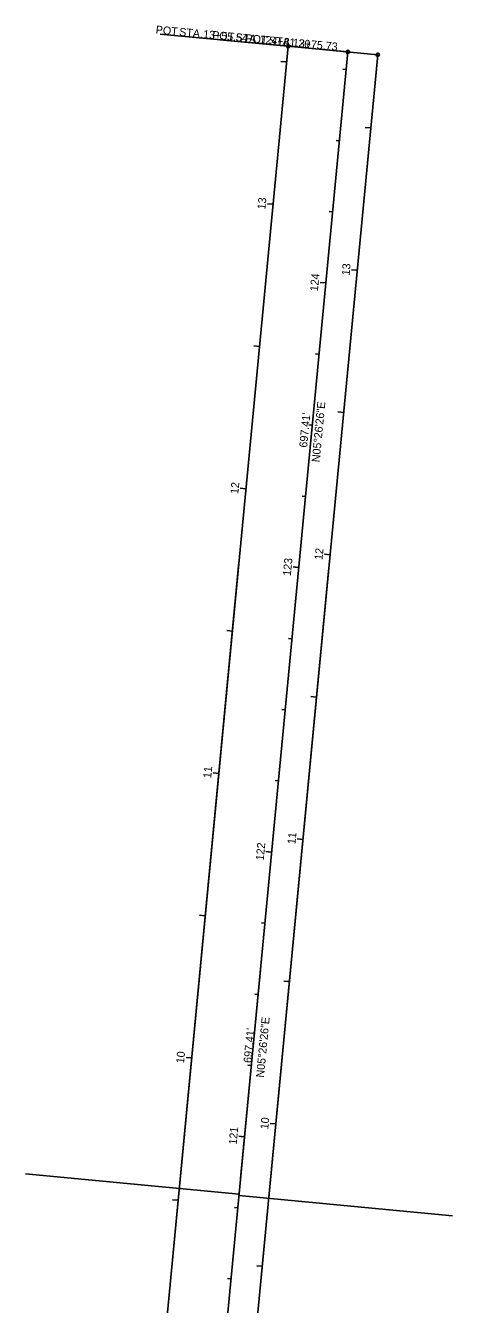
# Model space of a CAD drawing. Extents: x 1363416 to 1365241, y 422393 to 423801.
# Drawn here: x 1364196.5 to 1364345.8, y 423354 to 423801.4 of the extents above; entities that cross this region are included whole.
import ezdxf

# ---------------------------------------------------------------- set-up
doc = ezdxf.new("R2010")
doc.units = 0
for name, color, linetype in [('_CIVIL_CONSTRUCTION', 7, 'Continuous'), ('Default', 7, 'Continuous'), ('DT_X_Break_Line', 7, 'Continuous'), ('DT_X_Contour_Major', 7, 'Continuous'), ('DT_X_Contour_Minor', 7, 'Continuous'), ('DT_X_Island', 7, 'Continuous'), ('DT_X_Triangles', 7, 'Continuous'), ('MD_P_CURB_FACE_FL', 7, 'Continuous'), ('MD_P_CURB_FACE_TOP', 7, 'Continuous'), ('MD_P_PGL', 7, 'Continuous'), ('MD_P_SAWCUT', 7, 'Continuous'), ('PF_X_Ground_Line', 7, 'Continuous')]:
    doc.layers.add(name, color=color, linetype=linetype)

msp = doc.modelspace()

# ---------------------------------------------------------------- linework, layer by layer
at = {"layer": '_CIVIL_CONSTRUCTION'}
msp.add_line((1364243.11, 423097.89), (1364309.23, 423792.15), dxfattribs=at)
at = {"layer": 'Default'}
msp.add_line((1364232.49, 422986.41), (1364309.23, 423792.15), dxfattribs=at)
at = {"layer": 'DT_X_Break_Line'}
for p, q in [((1364288.32, 423794.14), (1364243.53, 423798.41)), ((1364319.68, 423791.16), (1364274.88, 423795.42)), ((1364222.2, 423099.88), (1364288.32, 423794.14)), ((1364228.76, 423168.72), (1364288.32, 423794.14)), ((1364228.76, 423168.72), (1364288.32, 423794.14)), ((1364253.56, 423096.89), (1364319.68, 423791.16)), ((1364259.98, 423164.33), (1364319.68, 423791.16)), ((1364259.98, 423164.33), (1364319.68, 423791.16)), ((1364287.8, 423788.63), (1364285.81, 423788.82)), ((1364317.24, 423765.55), (1364315.25, 423765.73)), ((1364283.06, 423738.85), (1364281.07, 423739.04)), ((1364312.5, 423715.77), (1364310.51, 423715.96)), ((1364278.32, 423689.08), (1364276.33, 423689.27)), ((1364307.76, 423666), (1364305.77, 423666.19)), ((1364273.58, 423639.3), (1364271.58, 423639.49)), ((1364303.02, 423616.22), (1364301.03, 423616.41)), ((1364228.76, 423168.72), (1364271.12, 423613.54)), ((1364228.76, 423168.72), (1364271.12, 423613.54)), ((1364259.98, 423164.33), (1364302.48, 423610.55)), ((1364259.98, 423164.33), (1364302.48, 423610.55)), ((1364268.83, 423589.53), (1364266.84, 423589.72)), ((1364298.28, 423566.45), (1364296.29, 423566.64)), ((1364264.09, 423539.75), (1364262.1, 423539.94)), ((1364293.54, 423516.67), (1364291.55, 423516.86)), ((1364259.35, 423489.98), (1364257.36, 423490.17)), ((1364288.8, 423466.9), (1364286.81, 423467.09)), ((1364254.61, 423440.2), (1364252.62, 423440.39)), ((1364284.06, 423417.12), (1364282.07, 423417.31)), ((1364249.87, 423390.43), (1364247.88, 423390.62)), ((1364279.32, 423367.35), (1364277.33, 423367.54))]:
    msp.add_line(p, q, dxfattribs=at)
for centre in [(1364288.32, 423794.14), (1364319.68, 423791.16)]:
    msp.add_circle(centre, 0.6, dxfattribs=at)
at = {"layer": 'DT_X_Contour_Major'}
for p, q in [((1364308.64, 423785.98), (1364307.45, 423786.09)), ((1364306.27, 423761.09), (1364305.08, 423761.21)), ((1364303.9, 423736.21), (1364302.71, 423736.32)), ((1364301.53, 423711.32), (1364299.54, 423711.51)), ((1364299.16, 423686.43), (1364297.96, 423686.54)), ((1364296.79, 423661.54), (1364295.59, 423661.66)), ((1364294.42, 423636.66), (1364293.22, 423636.77)), ((1364292.05, 423611.77), (1364290.06, 423611.96)), ((1364289.68, 423586.88), (1364288.48, 423587)), ((1364287.31, 423561.99), (1364286.11, 423562.11)), ((1364284.94, 423537.11), (1364283.74, 423537.22)), ((1364282.57, 423512.22), (1364280.58, 423512.41)), ((1364280.2, 423487.33), (1364279, 423487.45)), ((1364277.83, 423462.44), (1364276.63, 423462.56)), ((1364275.46, 423437.56), (1364274.26, 423437.67)), ((1364273.09, 423412.67), (1364271.09, 423412.86)), ((1364270.72, 423387.78), (1364269.52, 423387.9)), ((1364268.35, 423362.89), (1364267.15, 423363.01))]:
    msp.add_line(p, q, dxfattribs=at)
at = {"layer": 'DT_X_Island'}
for p, q in [((1364271.69, 423398), (1364278.64, 423470.99)), ((1364271.17, 423392.53), (1364196.51, 423399.64)), ((1364196.51, 423399.64), (1364271.17, 423392.53)), ((1364271.13, 423392.11), (1364345.79, 423385))]:
    msp.add_line(p, q, dxfattribs=at)
at = {"layer": 'DT_X_Triangles'}
msp.add_line((1364309.23, 423792.15), (1364264.43, 423796.42), dxfattribs=at)
msp.add_circle((1364309.23, 423792.15), 0.6, dxfattribs=at)
at = {"layer": 'MD_P_CURB_FACE_TOP'}
msp.add_line((1364309.23, 423792.15), (1364264.43, 423796.42), dxfattribs=at)
msp.add_circle((1364309.23, 423792.15), 0.6, dxfattribs=at)
at = {"layer": 'MD_P_SAWCUT'}
for p, q in [((1364301.53, 423711.32), (1364300.33, 423711.43)), ((1364292.05, 423611.77), (1364290.85, 423611.88)), ((1364282.57, 423512.22), (1364281.37, 423512.33)), ((1364273.09, 423412.67), (1364271.89, 423412.78))]:
    msp.add_line(p, q, dxfattribs=at)

# ---------------------------------------------------------------- texts
at = {"layer": 'DT_X_Break_Line'}
for s, rotation, p in [('POT', 354.5595, (1364241.93, 423798.6)), (' STA. ', 354.5595, (1364249.1, 423797.92)), ('13+55.54', 354.5595, (1364258.51, 423797.02)), ('POT', 354.5595, (1364273.29, 423795.62)), (' STA. ', 354.5595, (1364280.46, 423794.93)), ('13+75.73', 354.5595, (1364289.87, 423794.04)), ('13', 84.5595, (1364280.36, 423736.94)), ('13', 84.5595, (1364309.81, 423713.86)), ('12', 84.5595, (1364270.88, 423637.39)), ('12', 84.5595, (1364300.33, 423614.31)), ('11', 84.5595, (1364261.41, 423537.97)), ('11', 84.5595, (1364290.86, 423514.88)), ('10', 84.5595, (1364251.91, 423438.22)), ('10', 84.5595, (1364281.36, 423415.14))]:
    msp.add_text(s, height=2.8, rotation=rotation, dxfattribs=at).set_placement(p)
at = {"layer": 'DT_X_Contour_Major'}
for s, p in [('124', (1364298.73, 423708.3)), ('123', (1364289.25, 423608.75)), ('122', (1364279.77, 423509.19)), ('121', (1364270.3, 423409.77))]:
    msp.add_text(s, height=2.8, rotation=84.5595, dxfattribs=at).set_placement(p)
at = {"layer": 'DT_X_Contour_Minor'}
msp.add_text("697.41'", height=2.8, rotation=84.5595, dxfattribs=at).set_placement((1364294.97, 423653.63))
at = {"layer": 'DT_X_Triangles'}
for s, p in [('POT', (1364261.65, 423796.73)), (' STA. ', (1364268.82, 423796.04)), ('124+81.20', (1364278.23, 423795.15))]:
    msp.add_text(s, height=2.8, rotation=354.5595, dxfattribs=at).set_placement(p)
at = {"layer": 'MD_P_CURB_FACE_FL'}
msp.add_text('N05°26\'26"E', height=2.8, rotation=84.5595, dxfattribs=at).set_placement((1364279.87, 423433.25))
at = {"layer": 'MD_P_CURB_FACE_TOP'}
for s, p in [('POT', (1364261.65, 423796.73)), (' STA. ', (1364268.82, 423796.04)), ('124+81.20', (1364278.23, 423795.15))]:
    msp.add_text(s, height=2.8, rotation=354.5595, dxfattribs=at).set_placement(p)
at = {"layer": 'MD_P_PGL'}
msp.add_text("697.41'", height=2.8, rotation=84.5595, dxfattribs=at).set_placement((1364275.49, 423438.37))
at = {"layer": 'PF_X_Ground_Line'}
msp.add_text('N05°26\'26"E', height=2.8, rotation=84.5595, dxfattribs=at).set_placement((1364299.35, 423648.51))

doc.saveas('drawing.dxf')
